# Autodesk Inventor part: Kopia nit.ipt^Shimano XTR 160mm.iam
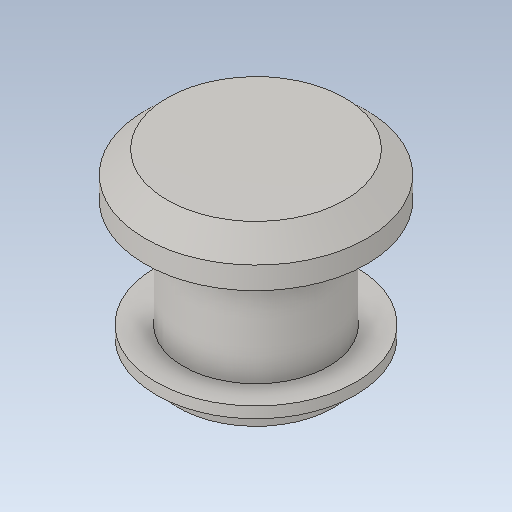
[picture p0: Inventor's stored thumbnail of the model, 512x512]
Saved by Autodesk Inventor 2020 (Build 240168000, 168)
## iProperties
Created: 2017-09
Part Number: Kopia nit.ipt^Shimano XTR 160mm.iam
Material: Ogólny
Document SubType Name: Modeling
Designer: Tomasz
Density: 1 g/cm^3
Appearance: Domyślna
Sending System: SolidWorks 2017
Last Author: Tomasz
Last Saved: 2017-09-11
Author: Tomasz
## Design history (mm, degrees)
feature "nit.ipt"
node "Bryła1"
